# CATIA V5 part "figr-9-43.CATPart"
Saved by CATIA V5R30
Part number: Part1
Bounding box of the stored display mesh (mm): x -60 to 60, y -70.327 to 65.87, z 0 to 125
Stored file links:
  D:\PROJECTS\CATIA V56R 2020\Resources\Parts File\c09_catia_v5_6r2020_prt\figr-9-43.CATPart
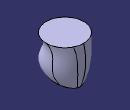
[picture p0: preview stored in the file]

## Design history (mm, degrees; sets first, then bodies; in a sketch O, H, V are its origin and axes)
Set1
  Plane1: type Offset, RefPlane xy-plane, Offset 125
Body1 (main body)
  Sketch1 on xy-plane, origin (0, 0, 0), H (1, 0, 0), V (0, 1, 0)
    ellipse A1 centre (0, 0) semi-axes 50, 30 rotation 270
    point P1 (30, 0)
    coincidence: P1 H, A1 P1
  Sketch2 on Plane1, origin (0, 0, 125), H (1, 0, 0), V (0, 1, 0)
    circle A1 centre (0, 0) radius 60
  Sketch3 on yz-plane, origin (0, 0, 0), H (0, 1, 0), V (0, 0, 1)
    arc A1 centre (-129.6632, 77.2731) radius 195.5761 from (50, 0) to (60, 125) ccw
    point P2 (50, 0)
    point P3 (60, 125)
    reference projected line E1 (-50, 0) -> (50, 0) from edge of Sketch1
    reference projected line E2 (-60, 125) -> (60, 125) from edge of Sketch2
    coincidence: P2 H, P2 E1, P3 E2
  Sketch4 on yz-plane, origin (0, 0, 0), H (0, 1, 0), V (0, 0, 1)
    spline S1 through (-50, 0) (-70, 40) (-50, 100) (-60, 125)
    reference projected line E1 (-60, 125) -> (60, 125) from edge of Sketch2
    reference projected line E2 (-50, 0) -> (50, 0) from edge of Sketch1
    point P1 (-60, 125)
    point P2 (-50, 0)
    coincidence: P1 E1, P2 E2
  Loft1: Sections (Sketch1; Sketch2), Guides (Sketch3; Sketch4)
